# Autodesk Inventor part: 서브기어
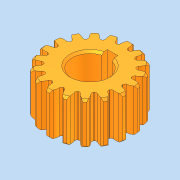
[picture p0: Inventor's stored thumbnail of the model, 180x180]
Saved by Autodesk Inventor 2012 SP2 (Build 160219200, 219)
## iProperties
Company: 한국ATC센터
Created: 2014-12
Part Number: 서브기어
Document SubType Name: Modeling
Designer: KYOUNG IL JANG
Density: 1 g/cm^3
Mass: 15.166 g
Surface Area: 69.6172 cm^2
Volume: 15.166 cm^3
Material: 기본값
Author: KYOUNG IL JANG
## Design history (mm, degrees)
sketch "스케치1"
  geometry: C1 r 15.5 at (0, 0); A1 r 1.155 centre (-2.906, 16.386) between (-2.542, 15.29) and (-1.751, 16.378); A2 r 5.602 centre (3.849, 16.522) between (-1.326, 18.666) and (-1.751, 16.378); A3 r 9.354 centre (7.378, 15.24) between (-0.682, 19.988) and (-1.326, 18.666); A4 r 1.155 centre (2.906, 16.386) between (1.751, 16.378) and (2.542, 15.29); A5 r 5.602 centre (-3.849, 16.522) between (1.751, 16.378) and (1.326, 18.666); A6 r 9.354 centre (-7.378, 15.24) between (1.326, 18.666) and (0.682, 19.988); A7 r 20 centre (0, 0) between (0.682, 19.988) and (-0.682, 19.988); A8 r 15.5 centre (0, 0) between (2.542, 15.29) and (-2.542, 15.29); 1 further point
  constraints: 16 point on circle, 9 centre point, 2 coincident
extrude "돌출1" new body sketch "스케치1" stored distance "d0" = 20; taper "d1" = 0 deg
extrude "돌출2" join sketch "스케치1" stored distance "d2" = 20; taper "d3" = 0 deg
chamfer "모따기1" distance "d4" = 1; stored, may be unused: second distance "d5" = 2, angle "d6" = 45 deg
hole "구멍1" diameter "d12" = 17; stored, may be unused: countersink angle "d16" = 90 deg, drill point angle "d18" = 118 deg; dims "d10" = 10, "d11" = 10, "d13" = 6, "d14" = 4, "d15" = 2, "d17" = 8
sketch "스케치2"
  geometry: L1 (-2.5, 8.124)-(-2.5, 10.8); L2 (-2.5, 10.8)-(2.5, 10.8); L3 (2.5, 10.8)-(2.5, 8.124); A1 r 8.5 centre (0, 0) between (-2.5, 8.124) and (2.5, 8.124) reference; 1 further point
  constraints: 6 end point, 2 parallel, 2 point on circle, 1 horizontal, 1 vertical
  dimensions: "d22" = 5 distance of L1.end L2.end; "d23" = 2.3 distance edge to line of A1 L2
extrude "돌출3" cut sketch "스케치2" stored distance "d24" = 20; taper "d25" = 0 deg
chamfer "모따기2" distance "d19" = 1; stored, may be unused: second distance "d20" = 2, angle "d21" = 45 deg
node "솔리드1"
pattern_circular "원형 패턴1" dims angle "d8" = 360 deg
